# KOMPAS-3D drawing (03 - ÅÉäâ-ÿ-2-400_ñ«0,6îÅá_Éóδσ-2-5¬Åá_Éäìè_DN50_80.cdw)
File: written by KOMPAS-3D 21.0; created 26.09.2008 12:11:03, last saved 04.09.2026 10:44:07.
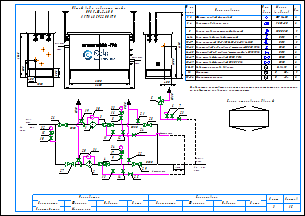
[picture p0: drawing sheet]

Sheets 1-2: A3, landscape

Document properties: Наименование: Макро:21; Автор: RaskoAdmin; Форматы листов документа: 2xA3; Полное имя файла: \\UR38nt01\Departments\КТО\КБ ПУРДГ\Заявки\Прайс-лист на типовые шкафы ГРПШ\ПРДГ_стандарт_20_03_2026\ПРДГ с РДНК\ПРДГ-Ш-2-400_до0,6МПа_Рвых-2-5кПа_РДНК_DN50_80.cdw

Title block, sheet 1: Наименование: Пункт учета газа / ПУГ-Ш-400-Р / ЛГТИ.485922.001ТУ; designation: ЛГТИ.03.4411141; sheet number: 1; Количество листов документа: 2; organisation: ООО "ЭЛЬСТЕР Газэлектроника"; Форматы листов документа: A3; stored path: C:\Рабочие документы\Компас\ПУГ\Схема.cdw; Разработал: Устинов; Проверил: Кошкин; Утвердил: Кошкин
Title block, sheet 2: sheet number: 2; stored path: D:\Рабочие документы\Заявки\ПУРДГ\ПУРДГ-ШУЭО-2-100-Р 4411220.cdw; designation, second copy: ЛГТИ.03.4411141-

Views: Вид 1, Вид 2
Referenced files: wcvoit.frw
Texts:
  Normal
  Вход
  газа
  PDI
  Выход
  Р=     кПа
  DN80
  DN50
  DN20
  Импульс DN15
  ≥5DN
  HYSWLongFangSong
  № на
  схеме
  Усл.
  обозн.
  Марка
  (модель)
  Кол.
  Фильтр газовый фланцевый
  ФГ 16-50
  Регулятор давления газа
  РДНК-50
  Клапан предохранительный сбросной
  КПС DN20
  Кран шаровой газовый латунный
  DN15
  Кран кнопочный VE-РАСКО-НЗ-1,6-G1/2-М20
  Кран шаровой "под приварку" штуцерный DN20 PN16
  Кран шаровой "под приварку" штуцерный п/п DN15 PN16
  Кран шаровой фланцевый DN50 PN16
  Кран шаровой фланцевый DN80 PN16
  Индикатор перепада давления
  Delta 15
  Манометр
  Манометр-напоромер
  0...     МПа
  0...     кПа
  Общий вид и габариты шкафа
  ПРДГ-Ш-2-400
  Выход газа
  Вход газа
  Схема открывания дверей
  logo-rasko-ge.png
  Предприятие изготовитель может заменять комплектующие на аналогичные,
  не ухудшающие заявленных характеристик.
  Р=        МПа
  Должность
  Конструктор
  Фамилия
  Подпись
  Дата
  Согласовано
  Максимкин
  Лист
  Листов
  POLYLINE_STYLE_0.18_RGB_0_0_0
  POLYLINE_STYLE_0.50_RGB_0_0_0
  POLYLINE_STYLE_0.34_RGB_0_0_0
  PHANTOM_RGB_0_0_0_SC_1_THICK_0.18
  K5LT_THIN_RGB_0_0_0_THICK_0.18
  K5LT32769_RGB_0_0_0_THICK_0.18
  K5LT12_RGB_0_0_0_SC_1_THICK_0.18
  K5LT_DASHED_RGB_0_0_0_SC_1_THICK_0.18
  ACISOTGL_RGB_0_0_0_SC_0.8_THICK_0.25
  CONTINUOUS_RGB_0_127_31_THICK_0.3
  CONTINUOUS_RGB_0_0_255_THICK_0.35
  CONTINUOUS_RGB_255_0_0_THICK_0.35
  POLYLINE_STYLE_0.25_RGB_0_0_0
  CONTINUOUS_RGB_0_0_0_THICK_0.5
  POLYLINE_STYLE_0.35_RGB_0_0_255
  CONTINUOUS_RGB_0_0_0_THICK_0.4
  CONTINUOUS_RGB_0_0_0_THICK_0.35
  Без оформления
Dimensions and other numbers on the sheet: 1; 2; 3; 4; 5; 10; 27; 28; 29; 23; 8; 12; 19; 20; 21; 22; 25; 24; 30; 31; 15; 16; 26; 6; 7; 11; 14; 13; 33; 1, 2; 3, 4; 6-14; 9; 15-17; 18-23; 24-25; 26-27; 28-29; 30-31; 32; 33-34; 400; 1050; 500; 305; 2300; 1565; 2600; 17; 34; 1000; 4130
